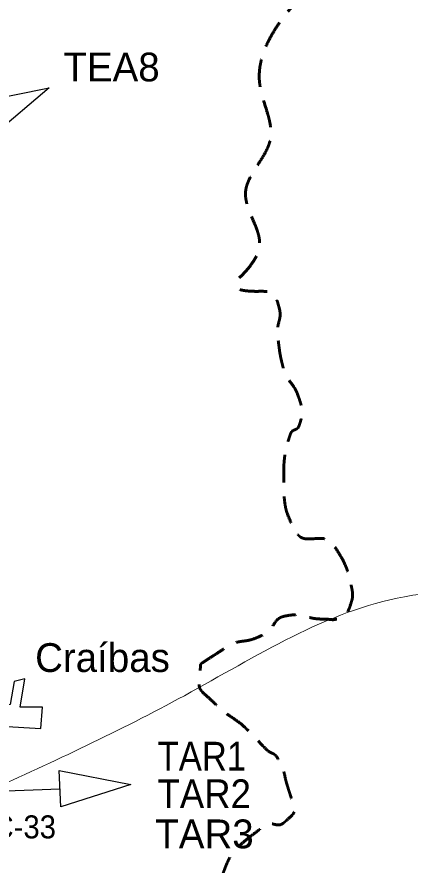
# Model space of a CAD drawing. Extents: x -1643653 to 4543381, y 1624270 to 13878484.
# Drawn here: x 745235 to 752066, y 8933563 to 8948296 of the extents above; entities that cross this region are included whole.
import ezdxf
from ezdxf.enums import TextEntityAlignment as Align

# ---------------------------------------------------------------- set-up
doc = ezdxf.new("R2010")
doc.units = 0
doc.header["$LTSCALE"] = 160
doc.linetypes.add('MEDIUM_DASHED', pattern=[4.5, 3, -1.5])
for name, color, linetype, lineweight in [('10', 7, 'MEDIUM_DASHED', 60), ('15', 7, 'Continuous', 25), ('21', 7, 'Continuous', 25), ('50', 7, 'Continuous', 13), ('54', 7, 'Continuous', 25), ('60', 7, 'Continuous', 13)]:
    doc.layers.add(name, color=color, linetype=linetype, lineweight=lineweight)
doc.layers.add('41', color=7, linetype='Continuous')

msp = doc.modelspace()

# ---------------------------------------------------------------- linework, layer by layer
at = {"layer": '10'}
msp.add_spline([(752064, 8949931.3), (749882.4, 8948312.2), (749452.3, 8947143.5), (749636.6, 8946159.4), (749206.6, 8945236.7), (749452.3, 8944375.6), (748941.6, 8943614.3)], degree=3, dxfattribs=at)
for points in [[(748428.7, 8937057.8), (748568.6, 8937148.3), (748708.4, 8937238.8), (748848.3, 8937329.4), (749030.7, 8937447.4), (749270.9, 8937454.9), (749465.4, 8937539.2), (749644.3, 8937616.8), (749748.6, 8937866), (749946.7, 8937897.2), (750151.5, 8937929.4), (750357.8, 8937840), (750563.7, 8937835.5), (750653.6, 8937833.5), (750744.1, 8937817.7), (750834, 8937851.6), (750948, 8937894.7), (751009.1, 8938011), (751043.8, 8938123.2), (751073.8, 8938220), (751064.4, 8938323), (751043.8, 8938419.4), (750996.5, 8938641.1), (750911.9, 8938852.4), (750784.7, 8939049), (750625.7, 8939294.4), (750166, 8939169.6), (750031.8, 8939444), (749904.6, 8939704.2), (749874.5, 8939968.8), (749871.4, 8940234), (749868.3, 8940500.5), (749897, 8940771.6), (749982.5, 8941036.4), (750007.4, 8941113.5), (750119.1, 8941136.5), (750142.9, 8941209.2), (750187.9, 8941346.2), (750189.4, 8941516.7), (750142.9, 8941653.6), (750072.1, 8941862), (749901.7, 8942042.3), (749846.7, 8942262.3), (749811.1, 8942404.7), (749791.8, 8942550), (749772.7, 8942694.3), (749745.7, 8942897.4), (749833.2, 8943109.7), (749772.7, 8943311.5), (749686.1, 8943600.2), (749223.6, 8943490.5), (748941.6, 8943614.3)], [(753774.9, 8926261.4), (753812.7, 8926399.9), (753812, 8926558.8), (753709.5, 8926687.3), (753566, 8926867.3), (753376.7, 8926916.9), (753227, 8927050.3), (753014.8, 8927239.4), (752804.9, 8927430.3), (752597.6, 8927630.5), (752376.7, 8927843.7), (752192.2, 8928091.3), (752017.6, 8928334.1), (751956, 8928419.6), (752103.6, 8928574.9), (752029.9, 8928655), (751955.6, 8928735.8), (751801.6, 8928688.1), (751721.4, 8928753.8), (751652.2, 8928810.4), (751601.3, 8928901.2), (751523.9, 8928951.3), (751367.8, 8929052.4), (751185.2, 8929119.1), (751030.2, 8929222.8), (750931.1, 8929289.2), (750854.8, 8929393), (750746.4, 8929445), (750665, 8929484.1), (750582.4, 8929520.3), (750499.6, 8929556.1), (750413.3, 8929593.4), (750326.8, 8929630.1), (750240.4, 8929667.2), (750059.5, 8929745.1), (749875.6, 8929807.6), (749709.7, 8929926.4), (749552.8, 8930038.9), (749714.4, 8930314.8), (749771.5, 8930481.9), (749848.6, 8930707.8), (750077.8, 8930926.7), (750119.5, 8931152.3), (750152, 8931328.4), (750058.1, 8931532.9), (749922, 8931707.8), (749753.2, 8931924.7), (749391.3, 8931773.6), (749243.2, 8931979.4), (749032.7, 8932271.9), (748906.3, 8932592.6), (748823.6, 8932929.9), (748786.3, 8933082.2), (748758.3, 8933247.9), (748811.3, 8933399), (748934, 8933748.4), (749210.7, 8934002.5), (749514.7, 8934226), (749629.1, 8934310.1), (749795.5, 8934228.1), (749909.7, 8934329.8), (749982.5, 8934394.6), (750061.5, 8934468.6), (750045.4, 8934552), (750025.6, 8934654.5), (749991.4, 8934758.2), (749959, 8934860.6), (749901, 8935043.9), (749870.4, 8935232.4), (749773.9, 8935403.7), (749725.3, 8935490), (749619.5, 8935521), (749551.8, 8935588.9), (749459.7, 8935681.1), (749373.5, 8935781.5), (749280.2, 8935872.8), (749090.8, 8936058.2), (748862, 8936191), (748663.2, 8936378.9), (748545.5, 8936490.1), (748390.4, 8936617), (748404, 8936773.9), (748412.2, 8936868.5), (748420.5, 8936963.2), (748428.7, 8937057.8)]]:
    msp.add_open_spline(points, degree=3, dxfattribs=at)
at = {"layer": '21'}
msp.add_lwpolyline([(745187, 8936748.8), (745117.1, 8936352.5), (744378.8, 8936344.3), (744279.6, 8936014.5), (745653.1, 8935932.8), (745681.3, 8936302.9), (745288.9, 8936302.6), (745373.5, 8936795.4)], close=True, dxfattribs=at)
at = {"layer": '50'}
msp.add_spline([(744731.4, 8934840.9), (748144.5, 8936505), (751968, 8938225.1), (754398.4, 8938284.4)], degree=3, dxfattribs=at)
at = {"layer": '54'}
msp.add_line((744753.2, 8934837.8), (745983.2, 8934887.6), dxfattribs=at)
for points in [[(744556.1, 8946816.5), (745797.1, 8947064.8), (744820.2, 8946242.8)], [(745970.4, 8935203.1), (747212.4, 8934959.8), (745996, 8934572.2)]]:
    msp.add_lwpolyline(points, close=True, dxfattribs=at)
at = {"layer": '60', "lineweight": 25}
msp.add_spline([(814781, 9009175.5), (814787.2, 9009173.4), (814796.9, 9009173.4), (814799.4, 9009172.4), (814805.1, 9009174.5), (814805.6, 9009176.5), (814811.7, 9009179.5), (814811.7, 9009179.5), (814801.5, 9009181), (814790.7, 9009181.5), (814784.1, 9009183.1), (814777.4, 9009185.1), (814778.4, 9009175.5)], degree=3, dxfattribs=at)

# ---------------------------------------------------------------- texts
at = {"layer": '15', "width": 0.95}
msp.add_text('C-33', height=400, dxfattribs=at).set_placement((744811.7, 8934025.6))
at = {"layer": '41'}
msp.add_text('Craíbas', height=500, dxfattribs=at).set_placement((745551.3, 8936916.9))
at = {"layer": '54'}
for s, p in [('TEA8', (746879.4, 8947176.6)), ('TAR3', (748493.9, 8933853.9))]:
    msp.add_text(s, height=500, dxfattribs=at).set_placement(p, align=Align.CENTER)
for s, width, p in [('TAR1', 0.9, (748448.4, 8935203.9)), ('TAR2', 0.95, (748489.3, 8934551.5))]:
    msp.add_text(s, height=500, dxfattribs=dict(at, width=width)).set_placement(p, align=Align.CENTER)

doc.saveas('drawing.dxf')
